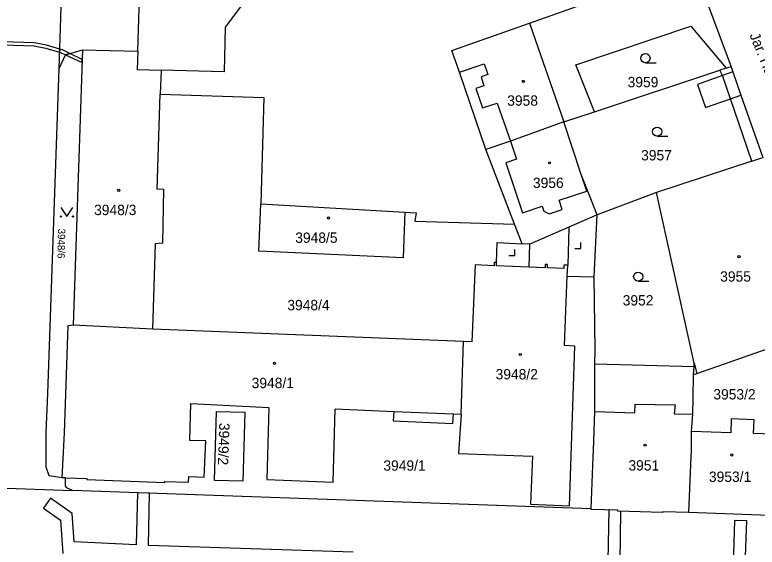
# Model space of a CAD drawing. Extents: x -756746 to -753363, y -1166406 to -1161727.
# Drawn here: x -756143.3 to -756021.2, y -1165633.6 to -1165546.1 of the extents above; entities that cross this region are included whole.
import ezdxf

# ---------------------------------------------------------------- set-up
doc = ezdxf.new("R2010")
doc.units = 0
for name, color, linetype in [('Hranice parcel', 7, 'Continuous'), ('Parcelní čísla', 7, 'Continuous'), ('Pop  PČ popisy', 7, 'Continuous'), ('Vnitřní kresba', 7, 'Continuous'), ('Věcná břemena k části', 7, 'Continuous'), ('Značky budov', 7, 'Continuous'), ('Značky kultur', 7, 'Continuous')]:
    doc.layers.add(name, color=color, linetype=linetype)

msp = doc.modelspace()

# ---------------------------------------------------------------- linework, layer by layer
at = {"layer": 'Hranice parcel'}
for p, q in [((-756132.19, -1165551.86), (-756133.69, -1165597.16)), ((-756026.32, -1165554.91), (-756027.36, -1165555.25)), ((-756047.97, -1165562.05), (-756027.36, -1165555.25)), ((-756053.01, -1165563.71), (-756047.97, -1165562.05)), ((-756061.12, -1165580.55), (-756065.85, -1165568.29)), ((-756022.13, -1165570.17), (-756020.3, -1165569.56)), ((-756022.13, -1165570.17), (-756037.8, -1165575.33)), ((-756037.8, -1165575.33), (-756047.56, -1165579.01)), ((-756102.85, -1165577.21), (-756079.17, -1165578.59)), ((-756048.05, -1165589.19), (-756047.56, -1165579.01)), ((-756052.46, -1165589.07), (-756048.05, -1165589.19)), ((-756120.6, -1165597.82), (-756133.69, -1165597.16)), ((-756069.51, -1165599.84), (-756120.6, -1165597.82)), ((-756069.93, -1165611.79), (-756069.51, -1165599.84)), ((-756031.61, -1165604), (-756047.9, -1165603.53)), ((-756031.7, -1165605.27), (-756031.61, -1165604)), ((-756134.98, -1165622.23), (-756135.55, -1165622.22)), ((-756156.38, -1165623.54), (-756133.84, -1165624.34)), ((-756048.5, -1165627.33), (-756133.84, -1165624.34)), ((-756019.22, -1165628.41), (-756032.46, -1165627.95))]:
    msp.add_line(p, q, dxfattribs=at)
for points in [[(-756136.03, -1165554.94), (-756135.51, -1165539.87), (-756135.36, -1165537.88)], [(-756065.85, -1165568.29), (-756070.17, -1165555.56), (-756071.45, -1165551.97), (-756058.66, -1165547.47), (-756031.75, -1165537.91)], [(-756031.75, -1165537.91), (-756025.53, -1165554.65), (-756026.32, -1165554.91)], [(-756047.97, -1165562.05), (-756051.04, -1165554.37), (-756032.11, -1165547.99), (-756026.32, -1165554.91)], [(-756136.03, -1165554.94), (-756135, -1165552.7), (-756132.19, -1165551.86)], [(-756132.19, -1165551.86), (-756123.07, -1165552.08), (-756123.2, -1165555.13), (-756119.26, -1165555.25), (-756119.39, -1165559.16)], [(-756135.55, -1165622.22), (-756137.67, -1165621.9), (-756138.18, -1165620.5), (-756138.14, -1165614.79), (-756137.88, -1165608.4), (-756136.03, -1165554.94)], [(-756022.13, -1165570.17), (-756025.62, -1165559.94), (-756026.93, -1165556.12), (-756027.36, -1165555.25)], [(-756120.6, -1165597.82), (-756120.16, -1165583.71), (-756118.95, -1165583.63), (-756118.82, -1165574.84), (-756119.88, -1165574.81), (-756119.39, -1165559.16)], [(-756119.39, -1165559.16), (-756102.36, -1165559.73), (-756102.85, -1165577.21)], [(-756053.01, -1165563.71), (-756061.78, -1165566.89), (-756065.85, -1165568.29)], [(-756047.56, -1165579.01), (-756050.15, -1165572.36), (-756053.01, -1165563.71)], [(-756031.61, -1165604), (-756031.57, -1165603.41), (-756037.8, -1165575.33)], [(-756079.17, -1165578.59), (-756079.47, -1165586.05), (-756103.18, -1165584.97), (-756102.85, -1165577.21)], [(-756079.17, -1165578.59), (-756077.28, -1165578.7), (-756077.51, -1165580.04), (-756061.12, -1165580.55)], [(-756047.56, -1165579.01), (-756052.19, -1165581.03), (-756058.59, -1165583.82), (-756059.86, -1165583.75), (-756061.12, -1165580.55)], [(-756052.46, -1165589.07), (-756052.37, -1165587.3), (-756053.01, -1165587.27), (-756053.04, -1165587.83), (-756055.73, -1165587.72), (-756055.7, -1165587.17), (-756056.07, -1165587.15), (-756056.09, -1165587.71), (-756058.73, -1165587.6), (-756064.09, -1165587.39), (-756064.07, -1165586.83), (-756064.46, -1165586.82), (-756064.48, -1165587.38), (-756067.63, -1165587.25), (-756068.13, -1165599.89), (-756069.51, -1165599.84)], [(-756069.93, -1165611.79), (-756070.34, -1165618.24), (-756058.17, -1165618.66), (-756058.49, -1165626.58), (-756052.11, -1165626.83), (-756051.23, -1165600.57), (-756052.89, -1165600.5), (-756052.46, -1165589.07)], [(-756047.9, -1165603.53), (-756047.89, -1165601.18), (-756048.05, -1165589.19)], [(-756133.69, -1165597.16), (-756134.58, -1165597.23), (-756134.98, -1165608.47), (-756135.2, -1165614.84), (-756135.55, -1165622.22)], [(-756031.7, -1165605.27), (-756031.13, -1165605.07), (-756018.16, -1165600.54)], [(-756048.5, -1165627.33), (-756048.19, -1165618.79), (-756048.15, -1165617.76), (-756047.92, -1165611.34), (-756047.9, -1165603.53)], [(-756032.02, -1165614.63), (-756031.8, -1165611.8), (-756031.76, -1165609.08), (-756031.7, -1165605.27)], [(-756134.98, -1165622.23), (-756131.47, -1165622.36), (-756131.47, -1165622.51), (-756118.65, -1165622.99), (-756118.65, -1165622.84), (-756114.74, -1165622.98), (-756114.71, -1165622.01), (-756112.17, -1165622.13), (-756111.92, -1165616.15), (-756114.55, -1165616.09), (-756114.38, -1165610), (-756101.51, -1165610.67), (-756101.86, -1165622.5), (-756090.93, -1165622.95), (-756090.63, -1165610.92), (-756081, -1165611.33), (-756081.07, -1165612.87), (-756071.26, -1165613.32), (-756071.19, -1165611.74), (-756069.93, -1165611.79)], [(-756110.48, -1165622.67), (-756110.16, -1165611.32), (-756105.47, -1165611.45), (-756105.82, -1165622.8), (-756110.48, -1165622.67)], [(-756018.65, -1165615.07), (-756021.84, -1165614.96), (-756021.73, -1165612.72), (-756025.51, -1165612.52), (-756025.56, -1165614.84), (-756032.02, -1165614.63)], [(-756032.46, -1165627.95), (-756032.1, -1165618.78), (-756032.05, -1165617.87), (-756032.02, -1165614.63)], [(-756133.84, -1165624.34), (-756134.77, -1165623.86), (-756134.98, -1165623.57), (-756134.98, -1165622.23)], [(-756032.46, -1165627.95), (-756036.81, -1165627.81), (-756036.81, -1165627.96), (-756044.16, -1165627.73), (-756044.15, -1165627.58), (-756048.5, -1165627.44), (-756048.5, -1165627.33)]]:
    msp.add_lwpolyline(points, dxfattribs=at)
at = {"layer": 'Vnitřní kresba'}
for p, q in [((-756123.07, -1165552.08), (-756122.62, -1165535.87)), ((-756106.2, -1165544.79), (-756108.7, -1165548.18)), ((-756058.66, -1165547.47), (-756053.01, -1165563.71)), ((-756108.7, -1165548.18), (-756108.87, -1165555.5)), ((-756070.17, -1165555.56), (-756066.1, -1165554.18)), ((-756066.1, -1165554.18), (-756065.5, -1165555.94)), ((-756025.53, -1165554.65), (-756025.23, -1165555.52)), ((-756108.87, -1165555.5), (-756119.26, -1165555.25)), ((-756065.5, -1165555.94), (-756066.63, -1165556.33)), ((-756026.93, -1165556.12), (-756031.04, -1165557.57)), ((-756025.23, -1165555.52), (-756026.93, -1165556.12)), ((-756025.23, -1165555.52), (-756023.89, -1165559.34)), ((-756066.63, -1165556.33), (-756066.17, -1165557.79)), ((-756066.17, -1165557.79), (-756067.48, -1165558.24)), ((-756067.48, -1165558.24), (-756066.42, -1165561.4)), ((-756031.04, -1165557.57), (-756029.71, -1165561.38)), ((-756029.71, -1165561.38), (-756025.62, -1165559.94)), ((-756025.62, -1165559.94), (-756023.89, -1165559.34)), ((-756023.89, -1165559.34), (-756020.3, -1165569.56)), ((-756066.42, -1165561.4), (-756063.98, -1165560.63)), ((-756063.98, -1165560.63), (-756061.78, -1165566.89)), ((-756061.78, -1165566.89), (-756060.79, -1165569.83)), ((-756060.79, -1165569.83), (-756062.58, -1165570.44)), ((-756062.58, -1165570.44), (-756062.07, -1165571.94)), ((-756062.07, -1165571.94), (-756059.81, -1165578.68)), ((-756049.25, -1165575.1), (-756050.15, -1165572.36)), ((-756053.78, -1165576.62), (-756049.25, -1165575.1)), ((-756053.28, -1165578.13), (-756053.78, -1165576.62)), ((-756059.81, -1165578.68), (-756056.56, -1165577.59)), ((-756056.56, -1165577.59), (-756056.29, -1165578.4)), ((-756055.43, -1165578.85), (-756053.28, -1165578.13)), ((-756056.29, -1165578.4), (-756055.43, -1165578.85)), ((-756052.19, -1165581.03), (-756052.37, -1165587.3)), ((-756064.07, -1165586.83), (-756063.97, -1165583.54)), ((-756063.97, -1165583.54), (-756059.86, -1165583.75)), ((-756058.73, -1165587.6), (-756058.59, -1165583.82)), ((-756031.57, -1165603.41), (-756031.13, -1165605.07)), ((-756041.35, -1165611.53), (-756041.31, -1165610.12)), ((-756041.31, -1165610.12), (-756034.71, -1165610.25)), ((-756034.71, -1165610.25), (-756034.89, -1165611.71)), ((-756081, -1165611.33), (-756071.19, -1165611.74)), ((-756047.92, -1165611.34), (-756041.35, -1165611.53)), ((-756034.89, -1165611.71), (-756031.8, -1165611.8))]:
    msp.add_line(p, q, dxfattribs=at)
at = {"layer": 'Věcná břemena k části'}
for points in [[(-756150.42, -1165550.9), (-756140.2, -1165551.24), (-756138.22, -1165551.59), (-756135.94, -1165552.27), (-756135.92, -1165551.76), (-756138.1, -1165551.11), (-756140.14, -1165550.74), (-756150.4, -1165550.4)], [(-756087.65, -1165634.44), (-756121.33, -1165633.34), (-756121.16, -1165624.78), (-756123.15, -1165624.71), (-756123.33, -1165633.26), (-756133.53, -1165632.76), (-756133.87, -1165628.08), (-756137.43, -1165625.61), (-756138.57, -1165627.25), (-756135.8, -1165629.18), (-756135.39, -1165634.68)], [(-756043.77, -1165635.95), (-756043.64, -1165627.75), (-756044.16, -1165627.73), (-756044.15, -1165627.58), (-756045.64, -1165627.53), (-756045.76, -1165635.88)], [(-756023.18, -1165636.58), (-756022.93, -1165629.3), (-756024.93, -1165629.24), (-756025.18, -1165636.52)]]:
    msp.add_lwpolyline(points, dxfattribs=at)
for points in [[(-756135, -1165552.7), (-756134.26, -1165552.48), (-756135.48, -1165551.89), (-756135.92, -1165551.76), (-756135.94, -1165552.27), (-756135.66, -1165552.35)], [(-756132.24, -1165553.46), (-756134.26, -1165552.48), (-756135, -1165552.7), (-756132.26, -1165553.99)]]:
    msp.add_lwpolyline(points, close=True, dxfattribs=at)
at = {"layer": 'Značky budov'}
for centre in [(-756059.67, -1165557.07), (-756055.39, -1165570.45), (-756126.22, -1165574.97), (-756091.71, -1165579.53), (-756024.21, -1165585.89), (-756060.18, -1165601.97), (-756100.6, -1165603.42), (-756039.68, -1165616.88), (-756025.4, -1165618.49)]:
    msp.add_circle(centre, 0.175, dxfattribs=at)
at = {"layer": 'Značky kultur'}
for p, q in [((-756039.6, -1165554), (-756037.85, -1165554)), ((-756037.67, -1165566.07), (-756035.92, -1165566.07)), ((-756050.23, -1165584.56), (-756050.23, -1165583.56)), ((-756061.07, -1165585.7), (-756061.07, -1165584.7)), ((-756051.23, -1165584.56), (-756050.23, -1165584.56)), ((-756062.07, -1165585.7), (-756061.07, -1165585.7)), ((-756040.79, -1165589.92), (-756039.04, -1165589.92))]:
    msp.add_line(p, q, dxfattribs=at)
msp.add_lwpolyline([(-756135.75, -1165577.78), (-756134.75, -1165579.28), (-756133.75, -1165577.78)], dxfattribs=at)
for centre, radius in [((-756039.6, -1165553.25), 0.75), ((-756037.67, -1165565.32), 0.75), ((-756135.75, -1165579.28), 0.1), ((-756133.75, -1165579.28), 0.1), ((-756040.79, -1165589.17), 0.75)]:
    msp.add_circle(centre, radius, dxfattribs=at)

# ---------------------------------------------------------------- texts
at = {"layer": 'Parcelní čísla'}
for s, p in [('3959', (-756042.53, -1165558.03)), ('3958', (-756062.33, -1165561.07)), ('3957', (-756040.31, -1165570.06)), ('3956', (-756058.1, -1165574.59)), ('3948/3', (-756130.27, -1165579.05)), ('3948/5', (-756097.19, -1165583.61)), ('3955', (-756027.31, -1165589.99)), ('3948/4', (-756098.49, -1165594.69)), ('3952', (-756043.34, -1165593.91)), ('3948/2', (-756064.24, -1165606.06)), ('3948/1', (-756104.36, -1165607.5)), ('3953/2', (-756028.43, -1165609.36)), ('3949/1', (-756082.7, -1165621.07)), ('3951', (-756042.4, -1165621.04)), ('3953/1', (-756029.16, -1165622.91))]:
    msp.add_text(s, height=1.7, dxfattribs=at).set_placement(p)
for s, height, rotation, p in [('3948/6', 1.2, 269, (-756136.21, -1165581.26)), ('3949/2', 1.7, 268, (-756109.68, -1165613.18))]:
    msp.add_text(s, height=height, rotation=rotation, dxfattribs=at).set_placement(p)
at = {"layer": 'Pop  PČ popisy'}
msp.add_text('Jar. Haška', height=1.7, rotation=292, dxfattribs=at).set_placement((-756022.51, -1165549.46))

doc.saveas('drawing.dxf')
